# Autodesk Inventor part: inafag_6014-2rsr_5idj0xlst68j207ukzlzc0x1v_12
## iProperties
Shininess: 64.0
Angle Display Precision: 2
Document Length Units: 11269
Document Angle Units: 11279
Document Time Units: 11290
Document Mass Units: 11283
Document Length Units Precision: 3
Document Angle Units Precision: 2
Compacted: True
Created: 2008-08
Part Number: inafag_6014-2rsr_5idj0xlst68j207ukzlzc0x1v_12
Document SubType Name: Modeling
Designer: tpomodeler
Density: 0.0
Volumn: 0.0
Area: 0.0
PropertySet Name: Model Information
Control State: 0
Master: False
Checked Out: False
Author: tpomodeler
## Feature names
1. inafag_6014-2rsr_5idj0xlst68j207ukzlzc0x1v
